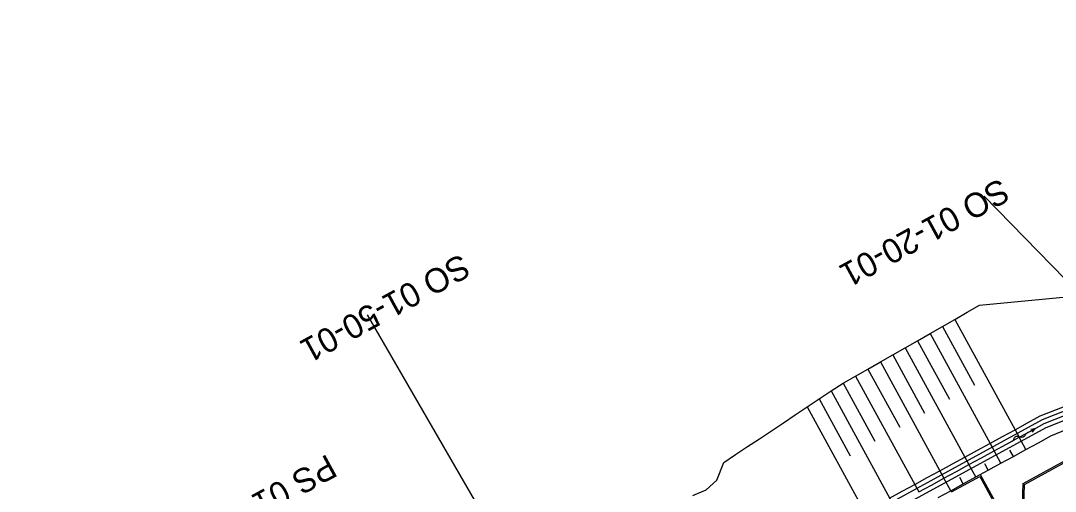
# Model space of a CAD drawing. Extents: x -783978 to -783565, y -1064821 to -1064596.
# Drawn here: x -783865.7 to -783793.3, y -1064691.8 to -1064658.9 of the extents above; entities that cross this region are included whole.
import ezdxf

# ---------------------------------------------------------------- set-up
doc = ezdxf.new("R2010")
doc.units = 0
doc.layers.add('_PS_SO_číslo', color=7, linetype='Continuous')
doc.layers.add('SO 01_50_01', color=7, linetype='Continuous')

# ---------------------------------------------------------------- blocks, each defined once
blk = doc.blocks.new('SIPKP')
at = {"layer": 'SO 01_50_01'}
for p, q in [((0, 0), (19.5, 0)), ((67.1, 0.2), (74.2, 0.2)), ((74.2, 0.2), (90.5, 0.2)), ((90.5, 0.2), (79.4, 4.9)), ((79.4, -4.1), (90.5, 0.2))]:
    blk.add_line(p, q, dxfattribs=at)
for centre, radius, start, end in [((19.6, -5.8), 5.82, 37.3192, 90.4169), ((51.6, -5.8), 11.1, 42.7386, 149.222), ((66.6, 17.1), 16.9, 245.3105, 271.7078), ((32.5, 4.2), 10.5, 218.0257, 335.7054)]:
    blk.add_arc(centre, radius, start, end, dxfattribs=at)

msp = doc.modelspace()

# ---------------------------------------------------------------- linework, layer by layer
at = {"layer": '_PS_SO_číslo'}
for p, q in [((-783780.677, -1064689.287), (-783798.29, -1064671.183)), ((-783829.51, -1064700.114), (-783841.476, -1064679.468))]:
    msp.add_line(p, q, dxfattribs=at)
at = {"layer": 'SO 01_50_01'}
for p, q in [((-783800.352, -1064679.801), (-783799.484, -1064679.304)), ((-783799.484, -1064679.304), (-783798.616, -1064678.808)), ((-783801.221, -1064680.297), (-783800.352, -1064679.801)), ((-783800.352, -1064679.801), (-783795.85, -1064688.045)), ((-783794.223, -1064686.815), (-783776.789, -1064679.885)), ((-783794.095, -1064687.087), (-783776.678, -1064680.164)), ((-783802.957, -1064681.289), (-783802.089, -1064680.793)), ((-783802.089, -1064680.793), (-783801.221, -1064680.297)), ((-783802.089, -1064680.793), (-783797.606, -1064689.004)), ((-783801.221, -1064680.297), (-783798.975, -1064684.411)), ((-783793.967, -1064687.359), (-783776.567, -1064680.442)), ((-783803.826, -1064681.786), (-783802.957, -1064681.289)), ((-783802.957, -1064681.289), (-783800.72, -1064685.386)), ((-783805.563, -1064682.778), (-783804.694, -1064682.282)), ((-783804.694, -1064682.282), (-783803.826, -1064681.786)), ((-783804.694, -1064682.282), (-783802.466, -1064686.362)), ((-783803.826, -1064681.786), (-783799.361, -1064689.962)), ((-783806.431, -1064683.275), (-783805.563, -1064682.778)), ((-783805.563, -1064682.778), (-783801.116, -1064690.921)), ((-783808.168, -1064684.267), (-783807.299, -1064683.771)), ((-783807.299, -1064683.771), (-783806.431, -1064683.275)), ((-783807.299, -1064683.771), (-783802.872, -1064691.879)), ((-783806.431, -1064683.275), (-783804.213, -1064687.337)), ((-783809.013, -1064684.806), (-783808.168, -1064684.267)), ((-783808.168, -1064684.267), (-783805.959, -1064688.313)), ((-783809.848, -1064685.364), (-783809.013, -1064684.806)), ((-783809.013, -1064684.806), (-783804.627, -1064692.838)), ((-783811.518, -1064686.478), (-783810.683, -1064685.921)), ((-783810.683, -1064685.921), (-783809.848, -1064685.364)), ((-783810.683, -1064685.921), (-783806.382, -1064693.796)), ((-783809.848, -1064685.364), (-783807.677, -1064689.34)), ((-783812.353, -1064687.035), (-783811.518, -1064686.478)), ((-783795.26, -1064687.039), (-783794.382, -1064686.56)), ((-783868.841, -1064727.56), (-783794.223, -1064686.815)), ((-783868.554, -1064728.087), (-783793.967, -1064687.359)), ((-783813.188, -1064687.592), (-783812.353, -1064687.035)), ((-783796.138, -1064687.519), (-783795.26, -1064687.039)), ((-783794.973, -1064687.566), (-783794.095, -1064687.087)), ((-783814.023, -1064688.149), (-783813.188, -1064687.592)), ((-783797.893, -1064688.477), (-783797.016, -1064687.998)), ((-783797.016, -1064687.998), (-783796.138, -1064687.519)), ((-783796.728, -1064688.525), (-783795.85, -1064688.045)), ((-783795.85, -1064688.045), (-783794.973, -1064687.566)), ((-783795.377, -1064688.912), (-783795.85, -1064688.045)), ((-783794.499, -1064688.433), (-783793.621, -1064687.954)), ((-783794.499, -1064688.433), (-783793.621, -1064687.954)), ((-783794.499, -1064688.433), (-783793.621, -1064687.954)), ((-783815.694, -1064689.263), (-783814.859, -1064688.706)), ((-783814.859, -1064688.706), (-783814.023, -1064688.149)), ((-783798.771, -1064688.956), (-783797.893, -1064688.477)), ((-783797.606, -1064689.004), (-783796.728, -1064688.525)), ((-783795.377, -1064688.912), (-783794.499, -1064688.433)), ((-783795.377, -1064688.912), (-783794.499, -1064688.433)), ((-783795.377, -1064688.912), (-783794.499, -1064688.433)), ((-783816.531, -1064689.817), (-783815.694, -1064689.263)), ((-783800.526, -1064689.915), (-783799.649, -1064689.436)), ((-783799.649, -1064689.436), (-783798.771, -1064688.956)), ((-783799.361, -1064689.962), (-783798.483, -1064689.483)), ((-783798.483, -1064689.483), (-783797.606, -1064689.004)), ((-783797.132, -1064689.871), (-783797.606, -1064689.004)), ((-783797.132, -1064689.871), (-783796.254, -1064689.392)), ((-783797.132, -1064689.871), (-783796.254, -1064689.392)), ((-783797.132, -1064689.871), (-783796.254, -1064689.392)), ((-783796.254, -1064689.392), (-783796.491, -1064688.958)), ((-783796.254, -1064689.392), (-783795.377, -1064688.912)), ((-783796.254, -1064689.392), (-783795.377, -1064688.912)), ((-783796.254, -1064689.392), (-783795.377, -1064688.912)), ((-783817.001, -1064691.043), (-783816.531, -1064689.817)), ((-783801.404, -1064690.394), (-783800.526, -1064689.915)), ((-783800.239, -1064690.442), (-783799.361, -1064689.962)), ((-783798.887, -1064690.829), (-783799.361, -1064689.962)), ((-783798.01, -1064690.35), (-783798.247, -1064689.917)), ((-783798.01, -1064690.35), (-783797.132, -1064689.871)), ((-783798.01, -1064690.35), (-783797.132, -1064689.871)), ((-783798.01, -1064690.35), (-783797.132, -1064689.871)), ((-783803.159, -1064691.353), (-783802.282, -1064690.873)), ((-783802.282, -1064690.873), (-783801.404, -1064690.394)), ((-783801.994, -1064691.4), (-783801.116, -1064690.921)), ((-783801.116, -1064690.921), (-783800.239, -1064690.442)), ((-783800.643, -1064691.788), (-783801.116, -1064690.921)), ((-783799.765, -1064691.309), (-783800.002, -1064690.876)), ((-783799.765, -1064691.309), (-783798.887, -1064690.829)), ((-783799.765, -1064691.309), (-783798.887, -1064690.829)), ((-783799.765, -1064691.309), (-783798.887, -1064690.829)), ((-783799.717, -1064691.396), (-783798.608, -1064690.79)), ((-783798.887, -1064690.829), (-783798.01, -1064690.35)), ((-783798.887, -1064690.829), (-783798.01, -1064690.35)), ((-783798.887, -1064690.829), (-783798.01, -1064690.35)), ((-783818.692, -1064692.119), (-783817.768, -1064691.724)), ((-783817.768, -1064691.724), (-783817.001, -1064691.043)), ((-783804.037, -1064691.832), (-783803.159, -1064691.353)), ((-783802.872, -1064691.879), (-783801.994, -1064691.4)), ((-783800.643, -1064691.788), (-783799.765, -1064691.309)), ((-783800.643, -1064691.788), (-783799.765, -1064691.309)), ((-783800.643, -1064691.788), (-783799.765, -1064691.309)), ((-783800.595, -1064691.876), (-783799.717, -1064691.396)), ((-783804.915, -1064692.311), (-783804.037, -1064691.832)), ((-783801.52, -1064692.267), (-783800.643, -1064691.788)), ((-783801.52, -1064692.267), (-783800.643, -1064691.788)), ((-783801.52, -1064692.267), (-783800.643, -1064691.788))]:
    msp.add_line(p, q, dxfattribs=at)
for points in [[(-783794.382, -1064686.56), (-783780.883, -1064681.321), (-783774.1, -1064678.386), (-783769.133, -1064675.971), (-783757.845, -1064670.058), (-783751.352, -1064666.641), (-783737.229, -1064658.623), (-783727.849, -1064654.743)], [(-783793.621, -1064687.954), (-783787.363, -1064685.371), (-783777.547, -1064681.155), (-783771.548, -1064678.784), (-783764.589, -1064675.114), (-783753.212, -1064669.114), (-783738.363, -1064660.921), (-783736.402, -1064659.767), (-783727.433, -1064655.549)], [(-783798.616, -1064678.808), (-783769.133, -1064675.971)], [(-783798.608, -1064690.79), (-783796.451, -1064694.74), (-783795.57, -1064694.259), (-783795.465, -1064691.351), (-783789.473, -1064688.072)], [(-783798.568, -1064690.655), (-783796.411, -1064694.604), (-783795.668, -1064694.198), (-783795.563, -1064691.29), (-783789.521, -1064687.984)]]:
    msp.add_lwpolyline(points, dxfattribs=at)

# ---------------------------------------------------------------- block references
at = {"layer": 'SO 01_50_01', "xscale": 0.02497499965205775, "yscale": -0.02497499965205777, "rotation": 28.63656000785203}
msp.add_blockref('SIPKP', (-783796.728, -1064688.525), dxfattribs=at)

# ---------------------------------------------------------------- texts
at = {"layer": '_PS_SO_číslo'}
for s, p in [('SO 01-20-01', (-783797.157, -1064669.873)), ('SO 01-50-01', (-783834.912, -1064675.157)), ('PS 01-10-01', (-783844.263, -1064689.193))]:
    msp.add_text(s, height=1.7, rotation=208.68307, dxfattribs=at).set_placement(p)

doc.saveas('drawing.dxf')
